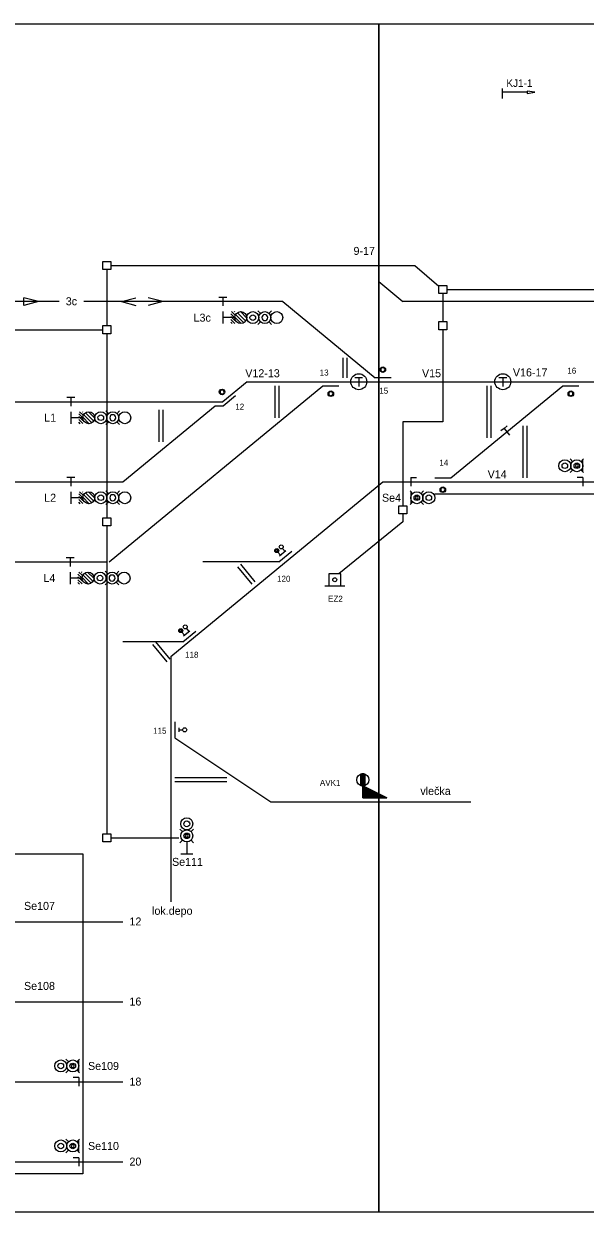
# Model space of a CAD drawing. Extents: x -1146 to 534, y 4 to 301.
# Drawn here: x -184.8 to -44.4, y 4.4 to 301.4 of the extents above; entities that cross this region are included whole.
import ezdxf

# ---------------------------------------------------------------- set-up
doc = ezdxf.new("R2010")
doc.units = 0
for name, color, linetype in [('formát tisku', 7, 'Continuous'), ('kabel', 7, 'Continuous'), ('koleje', 7, 'Continuous'), ('návěstidla', 7, 'Continuous'), ('popisy', 7, 'Continuous'), ('čd', 7, 'Continuous')]:
    doc.layers.add(name, color=color, linetype=linetype)

# ---------------------------------------------------------------- blocks, each defined once
blk = doc.blocks.new('NS5')
for p, q in [((-1, 5.5), (-1.7, 6.2)), ((1, 5.5), (1.7, 6.2)), ((-1, 3.5), (-1.7, 2.8)), ((0, 3), (0, 0)), ((1, 3.5), (1.7, 2.8)), ((-1.5, 0), (1.5, 0))]:
    blk.add_line(p, q)
for centre, radius in [((0, 7.5), 1.5), ((0, 4.5), 1.5), ((0, 7.5), 0.75), ((0, 4.5), 0.7)]:
    blk.add_circle(centre, radius)
for start, end in [(0, 180), (180, 0)]:
    blk.add_arc((0, 4.5), 0.375, start, end)
blk = doc.blocks.new('NS1')
for p, q in [((-1, 2.5), (-1.7, 3.2)), ((1, 2.5), (1.7, 3.2)), ((-1, 0.5), (-1.7, -0.2)), ((-1.5, 0), (1.5, 0)), ((1, 0.5), (1.7, -0.2))]:
    blk.add_line(p, q)
for centre, radius in [((0, 4.5), 1.5), ((0, 1.5), 1.5), ((0, 4.5), 0.7)]:
    blk.add_circle(centre, radius)
for start, end in [(0, 180), (180, 0)]:
    blk.add_arc((0, 1.5), 0.375, start, end)
blk = doc.blocks.new('SB4')
for q in [(-1.39, 1.08), (0, -1.08)]:
    blk.add_line((0, 1.08), q)
blk = doc.blocks.new('NS12')
for p, q in [((-1, 11.5), (-1.7, 12.2)), ((1, 11.5), (1.7, 12.2)), ((-1, 9.5), (-1.7, 8.8)), ((1, 9.5), (1.7, 8.8)), ((0.1, 6), (-1.5, 4.4)), ((0.8, 5.7), (-1.2, 3.7)), ((1.3, 5.25), (-0.8, 3.2)), ((1.5, 4.6), (-0.1, 3)), ((0, 3), (0, 0)), ((-1.5, 0), (1.5, 0))]:
    blk.add_line(p, q)
for centre, radius in [((0, 13.5), 1.5), ((0, 7.5), 1.5), ((0, 4.5), 1.5), ((0, 7.5), 0.7)]:
    blk.add_circle(centre, radius)
for start, end in [(0, 180), (180, 0)]:
    blk.add_arc((0, 10.5), 0.75, start, end)
blk = doc.blocks.new('NS16')
for p, q in [((-1.499, 0.6437), (-1.1298, 1.0129)), ((-1.4356, 0), (-0.4227, 1.0129)), ((-0.7285, 0), (0.2844, 1.0129)), ((-0.0214, 0), (0.9915, 1.0129)), ((0.6857, 0), (1.499, 0.8133)), ((1.3928, 0), (1.499, 0.1062))]:
    blk.add_line(p, q)
blk = doc.blocks.new('SB1')
for p, q in [((0, 1.08), (-1, 1.08)), ((1, 1.08), (0, 1.08)), ((0, 1.08), (0, -1.08))]:
    blk.add_line(p, q)
blk = doc.blocks.new('SB2')
for p, q in [((-0.03, 0.94), (-1.03, 0.94)), ((0.96, 0.94), (-0.04, 0.94)), ((-0.03, 0.94), (-0.03, -1.21))]:
    blk.add_line(p, q)
blk.add_circle((0, 0), 2)
blk = doc.blocks.new('PZ2')
for start, end in [(0, 180), (180, 0)]:
    blk.add_arc((0, 2), 0.5, start, end)
blk = doc.blocks.new('PZ11')
for p, q in [((-1.04, 1), (1.04, 1)), ((-0.74, 2), (-0.74, 1)), ((0.73, 1.98), (0.73, 1.01))]:
    blk.add_line(p, q)
blk.add_circle((0.73, 2.49), 0.5)
for start, end in [(0, 180), (180, 0)]:
    blk.add_arc((-0.73, 2.48), 0.25, start, end)
blk = doc.blocks.new('PZ9')
for p, q in [((-0.53, 1), (0.53, 1)), ((0, 1), (0, 1.97))]:
    blk.add_line(p, q)
blk.add_circle((0, 2.47), 0.5)
blk = doc.blocks.new('_X28')
for p, q in [((-3, 2.89), (-2.93, 2.96)), ((-3, 2.71), (-2.81, 2.9)), ((-3, 2.54), (-2.69, 2.85)), ((-3, 2.36), (-2.57, 2.79)), ((-3, 2.18), (-2.45, 2.73)), ((-3, 2.01), (-2.34, 2.67)), ((-3, 1.83), (-2.22, 2.61)), ((-3, 1.65), (-2.1, 2.55)), ((-3, 1.47), (-1.98, 2.49)), ((-3, 1.3), (-1.87, 2.43)), ((-3, 1.12), (-1.75, 2.37)), ((-3, 0.94), (-1.63, 2.31)), ((-3, 0.77), (-1.51, 2.26)), ((-3, 0.59), (-1.39, 2.2)), ((-3, 0.41), (-1.28, 2.14)), ((-3, 0.24), (-1.16, 2.08)), ((-3, 0.06), (-1.04, 2.02)), ((-2.88, 0), (-0.92, 1.96)), ((-2.71, 0), (-0.8, 1.9)), ((-2.53, 0), (-0.69, 1.84)), ((-2.35, 0), (-0.57, 1.78)), ((-2.18, 0), (-0.45, 1.73)), ((-2, 0), (-0.33, 1.67)), ((-1.82, 0), (-0.22, 1.61)), ((-1.65, 0), (-0.1, 1.55)), ((-1.47, 0), (0.02, 1.49)), ((-1.29, 0), (0.14, 1.43)), ((-1.12, 0), (0.26, 1.37)), ((-0.94, 0), (0.37, 1.31)), ((-0.76, 0), (0.49, 1.25)), ((-0.59, 0), (0.61, 1.2)), ((-0.41, 0), (0.73, 1.14)), ((-0.23, 0), (0.85, 1.08)), ((-0.06, 0), (0.96, 1.02)), ((0.12, 0), (1.08, 0.96)), ((0.3, 0), (1.2, 0.9)), ((0.47, 0), (1.32, 0.84)), ((0.65, 0), (1.43, 0.78)), ((0.83, 0), (1.55, 0.72)), ((1.01, 0), (1.67, 0.66)), ((1.18, 0), (1.79, 0.61)), ((1.36, 0), (1.91, 0.55)), ((1.54, 0), (2.02, 0.49)), ((1.71, 0), (2.14, 0.43)), ((1.89, 0), (2.26, 0.37)), ((2.07, 0), (2.38, 0.31)), ((2.24, 0), (2.5, 0.25)), ((2.42, 0), (2.61, 0.19)), ((2.6, 0), (2.73, 0.13)), ((2.77, 0), (2.85, 0.08)), ((2.95, 0), (2.97, 0.02))]:
    blk.add_line(p, q)
blk = doc.blocks.new('VU1')
blk.add_lwpolyline([(0, 1), (6, 1), (0, 4)], close=True)
blk.add_lwpolyline([(0, 4), (6, 1), (0, 1), (0, 4)])
blk.add_blockref('_X28', (3, 1))
blk = doc.blocks.new('_X30')
for p, q in [((-0.5, 0.47), (0.44, 1.41)), ((-0.5, 0.65), (0.26, 1.41)), ((-0.5, 0.83), (0.09, 1.41)), ((-0.5, 1.01), (-0.09, 1.41)), ((-0.5, 1.18), (-0.27, 1.41)), ((-0.5, 1.36), (-0.44, 1.41)), ((-0.5, 0.3), (0.5, 1.3)), ((-0.5, 0.12), (0.5, 1.12)), ((-0.5, -0.06), (0.5, 0.94)), ((-0.5, -0.23), (0.5, 0.77)), ((-0.5, -0.41), (0.5, 0.59)), ((-0.5, -0.59), (0.5, 0.41)), ((-0.5, -0.76), (0.5, 0.24)), ((-0.5, -0.94), (0.5, 0.06)), ((-0.5, -1.12), (0.5, -0.12)), ((-0.5, -1.29), (0.5, -0.29)), ((-0.44, -1.41), (0.5, -0.47)), ((-0.27, -1.41), (0.5, -0.65)), ((-0.09, -1.41), (0.5, -0.82)), ((0.09, -1.41), (0.5, -1)), ((0.26, -1.41), (0.5, -1.18)), ((0.44, -1.41), (0.5, -1.35))]:
    blk.add_line(p, q)
blk = doc.blocks.new('VU9')
for p, q in [((0, 3), (0, 0)), ((-0.5, 2.91), (-0.5, 0.09)), ((0, 2.91), (0, 0.09)), ((0.5, 2.91), (0.5, 0.09))]:
    blk.add_line(p, q)
blk.add_lwpolyline([(-0.5, 2.91), (0.5, 2.91), (0.5, 0.09), (-0.5, 0.09), (-0.5, 2.91)])
blk.add_circle((0, 1.5), 1.5)
for radius, start, end in [(1.5, 70.5288, 109.4712), (1.5, 250.5288, 289.4712), (1.25, 70.5288, 109.4712), (1.25, 250.5288, 289.4712)]:
    blk.add_arc((0, 1.5), radius, start, end)
blk.add_blockref('_X30', (0, 1.5))
blk = doc.blocks.new('PZ14')
for p, q in [((1.5, 3), (-1.5, 3)), ((-1.5, 3), (-1.5, 0)), ((1.5, 0), (1.5, 3)), ((-2.5, 0), (2.5, 0)), ((-1.5, 0), (1.5, 0))]:
    blk.add_line(p, q)
blk.add_circle((0, 1.5), 0.5)

msp = doc.modelspace()

# ---------------------------------------------------------------- linework, layer by layer
for p, q in [((-95.96, 301.44), (-95.96, 292.55)), ((-181.07, 232), (-184.7, 232.95)), ((-181.07, 232), (-184.7, 231.05)), ((-160.33, 232), (-156.7, 232.95)), ((-160.33, 232), (-156.7, 231.05)), ((-150.03, 232), (-153.66, 232.95)), ((-150.03, 232), (-153.66, 231.05)), ((-95.96, 4.44), (-95.96, 13.33))]:
    msp.add_line(p, q)
for centre, radius in [((-124.5, 228), 1.5), ((-95, 215), 0.7), ((-135.19, 209.44), 0.7), ((-108, 209), 0.7), ((-48, 209), 0.7), ((-162.5, 203), 1.5), ((-46.5, 191), 0.7), ((-162.5, 183), 1.5), ((-80, 185), 0.7), ((-86.5, 183), 0.7), ((-162.69, 162.93), 1.5), ((-144, 98.5), 0.7), ((-172.5, 41), 0.7), ((-172.5, 21), 0.7)]:
    msp.add_circle(centre, radius)
at = {"layer": 'formát tisku'}
for points in [[(-305.96, 301.44), (-95.96, 301.44), (-95.96, 4.44), (-305.96, 4.44)], [(-95.96, 301.44), (114.04, 301.44), (114.04, 4.44), (-95.96, 4.44)]]:
    msp.add_lwpolyline(points, close=True, dxfattribs=at)
at = {"layer": 'kabel'}
for p, q in [((-164, 240), (-164, 226)), ((-79, 235), (-3, 235)), ((-80, 234), (-80, 227)), ((-164, 224), (-164, 178)), ((-164, 176), (-164, 99)), ((-163, 98), (-146, 98))]:
    msp.add_line(p, q, dxfattribs=at)
for points in [[(-165, 242), (-163, 242), (-163, 240), (-165, 240)], [(-81, 236), (-79, 236), (-79, 234), (-81, 234)], [(-165, 226), (-163, 226), (-163, 224), (-165, 224)], [(-81, 227), (-79, 227), (-79, 225), (-81, 225)], [(-91, 181), (-89, 181), (-89, 179), (-91, 179)], [(-165, 178), (-163, 178), (-163, 176), (-165, 176)], [(-165, 99), (-163, 99), (-163, 97), (-165, 97)]]:
    msp.add_lwpolyline(points, close=True, dxfattribs=at)
for points in [[(-163, 241), (-87, 241), (-81, 235.88)], [(-226, 228), (-217, 228), (-217, 225), (-165, 225)], [(-80, 225), (-80, 202), (-90, 202), (-90, 181)], [(-82, 184), (-22, 184), (-22, 209), (9, 209)], [(-90, 179), (-90, 177), (-106, 164)], [(-325, 150), (-302, 150), (-302, 145), (-230, 145), (-230, 94), (-170, 94), (-170, 14), (-198, 14), (-273, 83), (-290, 66)]]:
    msp.add_lwpolyline(points, dxfattribs=at)
at = {"layer": 'koleje'}
for p, q in [((-96, 237), (-90, 232)), ((-175.87, 232), (-298, 232)), ((-120, 232), (-169.77, 232)), ((-120, 232), (-96.93, 213)), ((15, 232), (-90, 232)), ((-105, 218), (-105, 213)), ((-104, 218), (-104, 213)), ((-163.43, 167), (-110, 211)), ((-128.93, 212), (-135, 207)), ((-128.93, 212), (185.81, 212)), ((-122, 211), (-122, 203)), ((-121, 211), (-121, 203)), ((-110, 211), (-106, 211)), ((-92.93, 213), (-96.93, 213)), ((-78, 188), (-50, 211)), ((-69, 211), (-69, 198)), ((-68, 211), (-68, 198)), ((-50, 211), (-46, 211)), ((-134.93, 206), (-131.84, 208.54)), ((-298, 207), (-135, 207)), ((-160, 187), (-136.93, 206)), ((-151, 205), (-151, 197)), ((-150, 205), (-150, 197)), ((-136.93, 206), (-134.93, 206)), ((-60, 201), (-60, 188)), ((-59, 201), (-59, 188)), ((-82, 188), (-78, 188)), ((-298, 187), (-160, 187)), ((-148, 143.35), (-95, 187)), ((-95, 187), (-25, 187)), ((-121, 167), (-117.74, 169.68)), ((-245, 167), (-164, 167)), ((-121, 167), (-140, 167)), ((-130.59, 166.36), (-127, 162)), ((-131.36, 165.72), (-127.77, 161.36)), ((-145, 147), (-141.74, 149.68)), ((-145, 147), (-160, 147)), ((-152.59, 146.36), (-149, 142)), ((-151.82, 146.99), (-148.23, 142.64)), ((-148, 143.35), (-148, 82)), ((-147, 127), (-147, 123)), ((-147, 123), (-123, 107)), ((-134, 113), (-147, 113)), ((-134, 112), (-147, 112)), ((-123, 107), (-73, 107)), ((-237, 77), (-160, 77)), ((-216.67, 57), (-160, 57)), ((-210, 37), (-160, 37)), ((-188.67, 17), (-160, 17))]:
    msp.add_line(p, q, dxfattribs=at)
at = {"layer": 'popisy'}
for p, q in [((-65.04, 282.8), (-65.04, 285.27)), ((-58.88, 284.33), (-65.13, 284.33))]:
    msp.add_line(p, q, dxfattribs=at)
msp.add_lwpolyline([(-58.88, 284.64), (-58.88, 284.02), (-57, 284.33)], close=True, dxfattribs=at)
at = {"layer": 'čd'}
msp.add_line((-184.7, 231.05), (-184.7, 232.95), dxfattribs=at)
for centre in [(-121.51, 169.79), (-145.51, 149.79)]:
    msp.add_circle(centre, 0.5, dxfattribs=at)

# ---------------------------------------------------------------- block references
at = {"layer": 'návěstidla'}
for name, p, rotation in [('NS12', (-135, 228), -90.00000000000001), ('NS16', (-132, 228), 90), ('NS12', (-173, 203), -90.00000000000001), ('NS16', (-170, 203), 90), ('NS1', (-45, 191), 90.00000000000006), ('NS12', (-173, 183), -90.00000000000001), ('NS16', (-170, 183), 90), ('NS1', (-88, 183), -89.99999999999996), ('NS12', (-173.19, 162.93), -90.00000000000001), ('NS16', (-170.19, 162.93), 90), ('NS1', (-171, 41), 90.00000000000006), ('NS1', (-171, 21), 90.00000000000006)]:
    msp.add_blockref(name, p, dxfattribs=dict(at, rotation=rotation))
msp.add_blockref('NS5', (-144, 94), dxfattribs=at)
at = {"layer": 'čd'}
for name, p in [('SB1', (-135, 232)), ('SB2', (-101, 212)), ('PZ2', (-95, 213)), ('SB2', (-65, 212)), ('SB1', (-173, 207)), ('SB1', (-173, 187)), ('SB4', (-45, 187)), ('SB1', (-173.19, 166.93)), ('PZ14', (-107, 161)), ('VU9', (-100, 111)), ('VU1', (-100, 107)), ('SB4', (-171, 37)), ('SB4', (-171, 17))]:
    msp.add_blockref(name, p, dxfattribs=at)
for name, p, rotation in [('PZ2', (-133.91, 207.89), 39.472459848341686), ('PZ2', (-108, 211), 180), ('PZ2', (-48, 211), 180), ('SB1', (-64, 199.5), 39.400660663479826), ('PZ2', (-80, 187), 180), ('PZ11', (-119.37, 168.34), 39.47245984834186), ('PZ11', (-143.37, 148.34), 39.47245984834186), ('PZ9', (-147, 125), -90.00000000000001)]:
    msp.add_blockref(name, p, dxfattribs=dict(at, rotation=rotation))
at = {"layer": 'čd', "yscale": -1, "rotation": 180}
msp.add_blockref('SB4', (-88, 187), dxfattribs=at)

# ---------------------------------------------------------------- texts
for s, height, p in [('KJ1-1', 1.875, (-64.12, 285.67)), ('13', 1.5, (-110.78, 213.53)), ('16', 1.5, (-48.88, 214)), ('15', 1.5, (-95.88, 209)), ('12', 1.5, (-131.88, 205)), ('14', 1.5, (-80.88, 191)), ('120', 1.5, (-121.43, 162)), ('EZ2', 1.5, (-108.68, 157)), ('118', 1.5, (-144.43, 143)), ('115', 1.5, (-152.43, 124)), ('AVK1', 1.5, (-110.72, 111))]:
    msp.add_text(s, height=height).set_placement(p)
at = {"layer": 'popisy'}
for s, p in [('9-17', (-102.32, 243.68)), ('3c', (-174.25, 231.1)), ('L3c', (-142.3, 227)), ('V12-13', (-129.38, 213.11)), ('V15', (-85.2, 213.11)), ('V16-17', (-62.48, 213.31)), ('L1', (-179.64, 202)), ('V14', (-68.8, 187.88)), ('L2', (-179.64, 182)), ('Se4', (-95.21, 182)), ('L4', (-179.83, 161.93)), ('vlečka', (-85.61, 108.72)), ('Se111', (-147.69, 91)), ('Se107', (-184.69, 80)), ('lok.depo', (-152.68, 78.78)), ('12', (-158.33, 76.1)), ('Se108', (-184.69, 60)), ('16', (-158.33, 56.1)), ('Se109', (-168.69, 40)), ('18', (-158.33, 36.1)), ('Se110', (-168.69, 20)), ('20', (-158.33, 16.1))]:
    msp.add_text(s, height=2, dxfattribs=at).set_placement(p)

doc.saveas('drawing.dxf')
